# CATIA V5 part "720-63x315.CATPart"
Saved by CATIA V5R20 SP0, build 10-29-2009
Part number: 720-63x315
Definition: NONE
Nomenclature: 720-63x315
Source: Unknown
Description: 720-63x315
Bounding box of the stored display mesh (mm): x 0 to 315, y -31.5 to 31.5, z -31.5 to 31.5
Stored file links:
  C:\Users\Utente\Desktop\IO LAVORO\3D X SITO CF\X SITO\720\720-63x315.CATPart

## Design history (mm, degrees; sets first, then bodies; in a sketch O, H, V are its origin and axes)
Body1 "720-63x315" (main body)
  Solid1: solid without history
